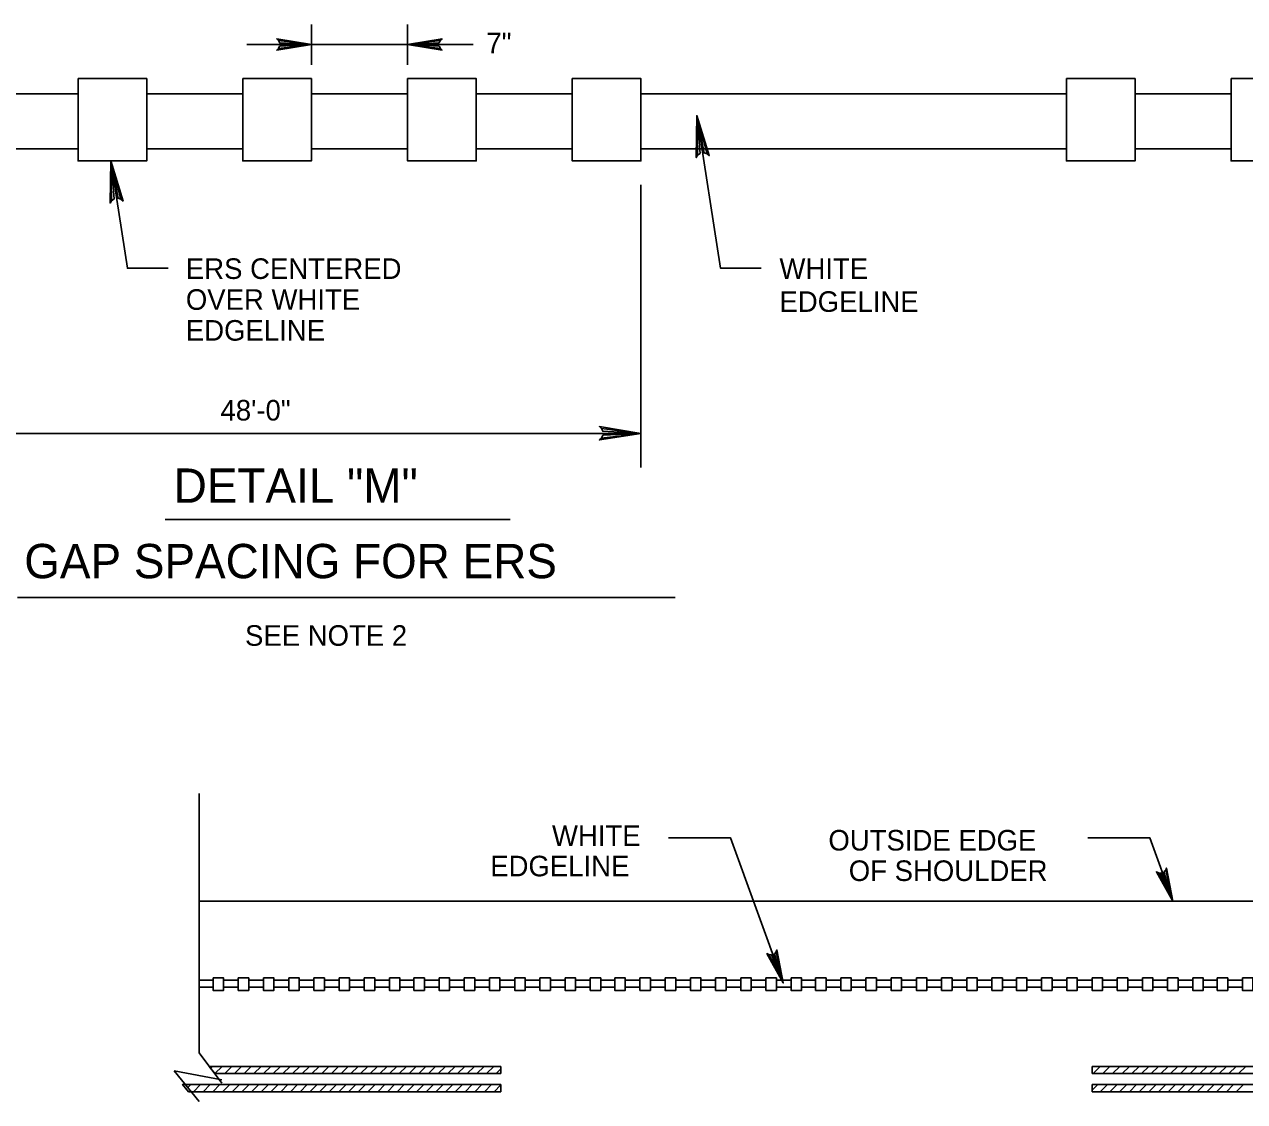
# Model space of a CAD drawing. Extents: x 632008 to 634206, y 294231 to 297795.
# Drawn here: x 632427 to 632604.8, y 296165.1 to 296322.1 of the extents above; entities that cross this region are included whole.
import ezdxf

# ---------------------------------------------------------------- set-up
doc = ezdxf.new("R2010")
doc.units = 0
for name, color, linetype in [('1', 7, 'Continuous'), ('Level 1', 7, 'Continuous'), ('Level 2', 7, 'Continuous')]:
    doc.layers.add(name, color=color, linetype=linetype)

msp = doc.modelspace()

# ---------------------------------------------------------------- linework, layer by layer
at = {"layer": '1'}
for p, q in [((632597.47, 296311.98), (632602.86, 296311.98)), ((632597.53, 296303.98), (632602.86, 296303.98)), ((632447.49, 296249.95), (632497.75, 296249.95)), ((632425.96, 296238.55), (632521.83, 296238.55)), ((632454.11, 296169.94), (632454.38, 296170.21)), ((632454.73, 296169.15), (632455.79, 296170.21)), ((632456.15, 296169.15), (632457.2, 296170.21)), ((632457.56, 296169.15), (632458.62, 296170.21)), ((632458.97, 296169.15), (632460.03, 296170.21)), ((632460.39, 296169.15), (632461.45, 296170.21)), ((632461.8, 296169.15), (632462.86, 296170.21)), ((632463.22, 296169.15), (632464.28, 296170.21)), ((632464.63, 296169.15), (632465.69, 296170.21)), ((632466.05, 296169.15), (632467.1, 296170.21)), ((632467.46, 296169.15), (632468.52, 296170.21)), ((632468.87, 296169.15), (632469.93, 296170.21)), ((632470.29, 296169.15), (632471.35, 296170.21)), ((632471.7, 296169.15), (632472.76, 296170.21)), ((632473.12, 296169.15), (632474.17, 296170.21)), ((632474.53, 296169.15), (632475.59, 296170.21)), ((632475.95, 296169.15), (632477, 296170.21)), ((632477.36, 296169.15), (632478.42, 296170.21)), ((632478.77, 296169.15), (632479.83, 296170.21)), ((632480.19, 296169.15), (632481.25, 296170.21)), ((632481.6, 296169.15), (632482.66, 296170.21)), ((632483.02, 296169.15), (632484.07, 296170.21)), ((632484.43, 296169.15), (632485.49, 296170.21)), ((632485.84, 296169.15), (632486.9, 296170.21)), ((632487.26, 296169.15), (632488.32, 296170.21)), ((632488.67, 296169.15), (632489.73, 296170.21)), ((632490.09, 296169.15), (632491.15, 296170.21)), ((632491.5, 296169.15), (632492.56, 296170.21)), ((632492.92, 296169.15), (632493.97, 296170.21)), ((632494.33, 296169.15), (632495.39, 296170.21)), ((632496.42, 296169.15), (632496.42, 296170.21)), ((632582.58, 296169.15), (632582.58, 296170.21)), ((632582.73, 296169.15), (632583.79, 296170.21)), ((632584.14, 296169.15), (632585.2, 296170.21)), ((632585.56, 296169.15), (632586.62, 296170.21)), ((632586.97, 296169.15), (632588.03, 296170.21)), ((632588.39, 296169.15), (632589.45, 296170.21)), ((632589.8, 296169.15), (632590.86, 296170.21)), ((632591.22, 296169.15), (632592.28, 296170.21)), ((632592.63, 296169.15), (632593.69, 296170.21)), ((632594.04, 296169.15), (632595.1, 296170.21)), ((632595.46, 296169.15), (632596.52, 296170.21)), ((632596.87, 296169.15), (632597.93, 296170.21)), ((632598.29, 296169.15), (632599.35, 296170.21)), ((632599.7, 296169.15), (632600.76, 296170.21)), ((632601.12, 296169.15), (632602.18, 296170.21)), ((632602.53, 296169.15), (632603.59, 296170.21)), ((632603.94, 296169.15), (632605, 296170.21)), ((632495.74, 296169.15), (632496.42, 296169.83)), ((632450.76, 296167.11), (632451.22, 296167.57)), ((632451.58, 296166.51), (632452.64, 296167.57)), ((632452.99, 296166.51), (632454.05, 296167.57)), ((632454.41, 296166.51), (632455.46, 296167.57)), ((632455.82, 296166.51), (632456.88, 296167.57)), ((632457.24, 296166.51), (632458.29, 296167.57)), ((632458.65, 296166.51), (632459.71, 296167.57)), ((632460.06, 296166.51), (632461.12, 296167.57)), ((632461.48, 296166.51), (632462.54, 296167.57)), ((632462.89, 296166.51), (632463.95, 296167.57)), ((632464.31, 296166.51), (632465.36, 296167.57)), ((632465.72, 296166.51), (632466.78, 296167.57)), ((632467.13, 296166.51), (632468.19, 296167.57)), ((632468.55, 296166.51), (632469.61, 296167.57)), ((632469.96, 296166.51), (632471.02, 296167.57)), ((632471.38, 296166.51), (632472.43, 296167.57)), ((632472.79, 296166.51), (632473.85, 296167.57)), ((632474.21, 296166.51), (632475.26, 296167.57)), ((632475.62, 296166.51), (632476.68, 296167.57)), ((632477.03, 296166.51), (632478.09, 296167.57)), ((632478.45, 296166.51), (632479.51, 296167.57)), ((632479.86, 296166.51), (632480.92, 296167.57)), ((632481.28, 296166.51), (632482.33, 296167.57)), ((632482.69, 296166.51), (632483.75, 296167.57)), ((632484.11, 296166.51), (632485.16, 296167.57)), ((632485.52, 296166.51), (632486.58, 296167.57)), ((632486.93, 296166.51), (632487.99, 296167.57)), ((632488.35, 296166.51), (632489.41, 296167.57)), ((632489.76, 296166.51), (632490.82, 296167.57)), ((632491.18, 296166.51), (632492.23, 296167.57)), ((632492.59, 296166.51), (632493.65, 296167.57)), ((632494, 296166.51), (632495.06, 296167.57)), ((632495.42, 296166.51), (632496.42, 296167.52)), ((632496.42, 296166.51), (632496.42, 296167.57)), ((632582.58, 296166.51), (632582.58, 296167.57)), ((632582.58, 296166.73), (632583.42, 296167.57)), ((632583.78, 296166.51), (632584.84, 296167.57)), ((632585.2, 296166.51), (632586.25, 296167.57)), ((632586.61, 296166.51), (632587.67, 296167.57)), ((632588.03, 296166.51), (632589.08, 296167.57)), ((632589.44, 296166.51), (632590.5, 296167.57)), ((632590.85, 296166.51), (632591.91, 296167.57)), ((632592.27, 296166.51), (632593.32, 296167.57)), ((632593.68, 296166.51), (632594.74, 296167.57)), ((632595.1, 296166.51), (632596.15, 296167.57)), ((632596.51, 296166.51), (632597.57, 296167.57)), ((632597.93, 296166.51), (632598.98, 296167.57)), ((632599.34, 296166.51), (632600.4, 296167.57)), ((632600.75, 296166.51), (632601.81, 296167.57)), ((632602.17, 296166.51), (632603.22, 296167.57)), ((632603.58, 296166.51), (632604.64, 296167.57))]:
    msp.add_line(p, q, dxfattribs=at)
for points in [[(632496.42, 296169.15), (632454.7, 296169.15), (632453.9, 296170.21), (632496.42, 296170.21)], [(632582.58, 296170.21), (632627.93, 296170.21), (632628.72, 296169.15), (632582.58, 296169.15)], [(632496.42, 296166.51), (632450.88, 296166.51), (632450.02, 296167.57), (632496.42, 296167.57)], [(632582.58, 296167.57), (632624.29, 296167.57), (632625.14, 296166.51), (632582.58, 296166.51)]]:
    msp.add_lwpolyline(points, dxfattribs=at)
at = {"layer": 'Level 1'}
for p, q in [((632434.78, 296311.98), (632420.77, 296311.98)), ((632458.79, 296311.98), (632444.78, 296311.98)), ((632482.8, 296311.98), (632468.79, 296311.98)), ((632506.81, 296311.98), (632492.81, 296311.98)), ((632578.85, 296311.98), (632516.82, 296311.98)), ((632597.47, 296311.98), (632588.85, 296311.98)), ((632434.78, 296303.98), (632420.77, 296303.98)), ((632458.79, 296303.98), (632444.78, 296303.98)), ((632482.8, 296303.98), (632468.79, 296303.98)), ((632506.81, 296303.98), (632492.81, 296303.98)), ((632578.85, 296303.98), (632516.82, 296303.98)), ((632597.53, 296303.98), (632588.85, 296303.98))]:
    msp.add_line(p, q, dxfattribs=at)
at = {"layer": 'Level 2'}
for p, q in [((632468.79, 296322.11), (632468.79, 296316.2)), ((632482.8, 296322.11), (632482.8, 296316.2)), ((632459.4, 296319.18), (632492.37, 296319.18)), ((632516.82, 296298.73), (632516.82, 296257.49)), ((632410.77, 296262.49), (632516.82, 296262.49)), ((632452.42, 296172.19), (632452.42, 296210)), ((632626.45, 296194.3), (632452.42, 296194.3)), ((632454.46, 296182.78), (632452.42, 296182.78)), ((632458.13, 296182.78), (632455.99, 296182.78)), ((632461.8, 296182.78), (632459.66, 296182.78)), ((632465.48, 296182.78), (632463.33, 296182.78)), ((632469.15, 296182.78), (632467.01, 296182.78)), ((632472.82, 296182.78), (632470.68, 296182.78)), ((632476.5, 296182.78), (632474.35, 296182.78)), ((632480.17, 296182.78), (632478.03, 296182.78)), ((632483.73, 296182.78), (632481.7, 296182.78)), ((632487.41, 296182.78), (632485.26, 296182.78)), ((632491.08, 296182.78), (632488.94, 296182.78)), ((632494.75, 296182.78), (632492.61, 296182.78)), ((632498.42, 296182.78), (632496.28, 296182.78)), ((632502.1, 296182.78), (632499.96, 296182.78)), ((632505.77, 296182.78), (632503.63, 296182.78)), ((632509.44, 296182.78), (632507.3, 296182.78)), ((632513.01, 296182.78), (632510.97, 296182.78)), ((632516.68, 296182.78), (632514.54, 296182.78)), ((632520.35, 296182.78), (632518.21, 296182.78)), ((632524.03, 296182.78), (632521.89, 296182.78)), ((632527.7, 296182.78), (632525.56, 296182.78)), ((632531.37, 296182.78), (632529.23, 296182.78)), ((632535.05, 296182.78), (632532.9, 296182.78)), ((632538.72, 296182.78), (632536.58, 296182.78)), ((632542.28, 296182.78), (632540.25, 296182.78)), ((632545.96, 296182.78), (632543.82, 296182.78)), ((632549.63, 296182.78), (632547.49, 296182.78)), ((632553.3, 296182.78), (632551.16, 296182.78)), ((632556.98, 296182.78), (632554.83, 296182.78)), ((632560.65, 296182.78), (632558.51, 296182.78)), ((632564.32, 296182.78), (632562.18, 296182.78)), ((632567.99, 296182.78), (632565.85, 296182.78)), ((632571.56, 296182.78), (632569.52, 296182.78)), ((632575.23, 296182.78), (632573.09, 296182.78)), ((632578.91, 296182.78), (632576.76, 296182.78)), ((632582.58, 296182.78), (632580.44, 296182.78)), ((632586.25, 296182.78), (632584.11, 296182.78)), ((632589.92, 296182.78), (632587.78, 296182.78)), ((632593.6, 296182.78), (632591.45, 296182.78)), ((632597.27, 296182.78), (632595.13, 296182.78)), ((632600.84, 296182.78), (632598.8, 296182.78)), ((632604.51, 296182.78), (632602.37, 296182.78)), ((632454.46, 296181.76), (632452.42, 296181.76)), ((632458.13, 296181.76), (632455.99, 296181.76)), ((632461.8, 296181.76), (632459.66, 296181.76)), ((632465.48, 296181.76), (632463.33, 296181.76)), ((632469.15, 296181.76), (632467.01, 296181.76)), ((632472.82, 296181.76), (632470.68, 296181.76)), ((632476.5, 296181.76), (632474.35, 296181.76)), ((632480.17, 296181.76), (632478.03, 296181.76)), ((632483.73, 296181.76), (632481.7, 296181.76)), ((632487.41, 296181.76), (632485.26, 296181.76)), ((632491.08, 296181.76), (632488.94, 296181.76)), ((632494.75, 296181.76), (632492.61, 296181.76)), ((632498.42, 296181.76), (632496.28, 296181.76)), ((632502.1, 296181.76), (632499.96, 296181.76)), ((632505.77, 296181.76), (632503.63, 296181.76)), ((632509.44, 296181.76), (632507.3, 296181.76)), ((632513.01, 296181.76), (632510.97, 296181.76)), ((632516.68, 296181.76), (632514.54, 296181.76)), ((632520.35, 296181.76), (632518.21, 296181.76)), ((632524.03, 296181.76), (632521.89, 296181.76)), ((632527.7, 296181.76), (632525.56, 296181.76)), ((632531.37, 296181.76), (632529.23, 296181.76)), ((632535.05, 296181.76), (632532.9, 296181.76)), ((632538.72, 296181.76), (632536.58, 296181.76)), ((632542.28, 296181.76), (632540.25, 296181.76)), ((632545.96, 296181.76), (632543.82, 296181.76)), ((632549.63, 296181.76), (632547.49, 296181.76)), ((632553.3, 296181.76), (632551.16, 296181.76)), ((632556.98, 296181.76), (632554.83, 296181.76)), ((632560.65, 296181.76), (632558.51, 296181.76)), ((632564.32, 296181.76), (632562.18, 296181.76)), ((632567.99, 296181.76), (632565.85, 296181.76)), ((632571.56, 296181.76), (632569.52, 296181.76)), ((632575.23, 296181.76), (632573.09, 296181.76)), ((632578.91, 296181.76), (632576.76, 296181.76)), ((632582.58, 296181.76), (632580.44, 296181.76)), ((632586.25, 296181.76), (632584.11, 296181.76)), ((632589.92, 296181.76), (632587.78, 296181.76)), ((632593.6, 296181.76), (632591.45, 296181.76)), ((632597.27, 296181.76), (632595.13, 296181.76)), ((632600.84, 296181.76), (632598.8, 296181.76)), ((632604.51, 296181.76), (632602.37, 296181.76)), ((632455.74, 296167.76), (632452.42, 296172.19)), ((632448.77, 296169.57), (632455.74, 296168.22)), ((632452.42, 296165.07), (632448.77, 296169.57))]:
    msp.add_line(p, q, dxfattribs=at)
for points in [[(632463.98, 296318.58), (632464.16, 296318.93), (632468.78, 296319.18), (632463.98, 296318.58), (632463.74, 296318.37), (632468.78, 296319.18), (632464.17, 296319.41), (632464, 296319.75), (632468.78, 296319.18), (632463.74, 296319.98), (632464, 296319.75)], [(632487.59, 296318.58), (632487.41, 296318.93), (632482.79, 296319.18), (632487.59, 296318.58), (632487.83, 296318.37), (632482.79, 296319.18), (632487.41, 296319.41), (632487.57, 296319.75), (632482.79, 296319.18), (632487.83, 296319.98), (632487.57, 296319.75)], [(632525.08, 296303.03), (632525.46, 296303.3), (632524.97, 296308.82), (632525.08, 296303.03), (632524.88, 296302.7), (632524.97, 296308.82), (632526.04, 296303.38), (632526.47, 296303.24), (632524.97, 296308.82), (632526.79, 296302.98), (632526.47, 296303.24)], [(632534.36, 296286.57), (632528.44, 296286.57), (632524.97, 296308.82)], [(632439.64, 296296.4), (632440.02, 296296.67), (632439.53, 296302.2), (632439.64, 296296.4), (632439.44, 296296.07), (632439.53, 296302.2), (632440.6, 296296.76), (632441.03, 296296.62), (632439.53, 296302.2), (632441.35, 296296.35), (632441.03, 296296.62)], [(632447.89, 296286.57), (632441.96, 296286.57), (632439.53, 296302.2)], [(632511.07, 296263.22), (632511.27, 296262.8), (632516.82, 296262.49), (632511.07, 296263.22), (632510.77, 296263.47), (632516.82, 296262.49), (632511.28, 296262.22), (632511.08, 296261.81), (632516.82, 296262.49), (632510.77, 296261.53), (632511.08, 296261.81)], [(632520.85, 296203.5), (632529.89, 296203.5), (632537.57, 296182.38)], [(632581.97, 296203.5), (632591.01, 296203.5), (632594.36, 296194.3)], [(632593.32, 296198.82), (632593.07, 296198.55), (632594.36, 296194.3), (632593.32, 296198.82), (632593.43, 296199.11), (632594.36, 296194.3), (632592.63, 296198.39), (632592.27, 296198.43), (632594.36, 296194.3), (632591.97, 296198.58), (632592.27, 296198.43)], [(632536.54, 296186.9), (632536.29, 296186.63), (632537.57, 296182.38), (632536.54, 296186.9), (632536.65, 296187.19), (632537.57, 296182.38), (632535.85, 296186.47), (632535.49, 296186.5), (632537.57, 296182.38), (632535.19, 296186.66), (632535.49, 296186.5)]]:
    msp.add_lwpolyline(points, dxfattribs=at)
for points in [[(632434.78, 296314.2), (632444.78, 296314.2), (632444.78, 296302.2), (632434.78, 296302.2)], [(632434.78, 296314.2), (632444.78, 296314.2), (632444.78, 296302.2), (632434.78, 296302.2)], [(632458.79, 296314.2), (632468.79, 296314.2), (632468.79, 296302.2), (632458.79, 296302.2)], [(632482.8, 296314.2), (632492.81, 296314.2), (632492.81, 296302.2), (632482.8, 296302.2)], [(632506.81, 296314.2), (632516.82, 296314.2), (632516.82, 296302.2), (632506.81, 296302.2)], [(632578.85, 296314.2), (632588.85, 296314.2), (632588.85, 296302.2), (632578.85, 296302.2)], [(632602.86, 296314.2), (632612.86, 296314.2), (632612.86, 296302.2), (632602.86, 296302.2)], [(632454.46, 296183.11), (632455.99, 296183.11), (632455.99, 296181.27), (632454.46, 296181.27)], [(632458.13, 296183.11), (632459.66, 296183.11), (632459.66, 296181.27), (632458.13, 296181.27)], [(632461.8, 296183.11), (632463.33, 296183.11), (632463.33, 296181.27), (632461.8, 296181.27)], [(632465.48, 296183.11), (632467.01, 296183.11), (632467.01, 296181.27), (632465.48, 296181.27)], [(632465.48, 296183.11), (632467.01, 296183.11), (632467.01, 296181.27), (632465.48, 296181.27)], [(632469.15, 296183.11), (632470.68, 296183.11), (632470.68, 296181.27), (632469.15, 296181.27)], [(632469.15, 296183.11), (632470.68, 296183.11), (632470.68, 296181.27), (632469.15, 296181.27)], [(632472.82, 296183.11), (632474.35, 296183.11), (632474.35, 296181.27), (632472.82, 296181.27)], [(632472.82, 296183.11), (632474.35, 296183.11), (632474.35, 296181.27), (632472.82, 296181.27)], [(632476.5, 296183.11), (632478.03, 296183.11), (632478.03, 296181.27), (632476.5, 296181.27)], [(632476.5, 296183.11), (632478.03, 296183.11), (632478.03, 296181.27), (632476.5, 296181.27)], [(632480.17, 296183.11), (632481.7, 296183.11), (632481.7, 296181.27), (632480.17, 296181.27)], [(632480.17, 296183.11), (632481.7, 296183.11), (632481.7, 296181.27), (632480.17, 296181.27)], [(632483.73, 296183.11), (632485.26, 296183.11), (632485.26, 296181.27), (632483.73, 296181.27)], [(632487.41, 296183.11), (632488.94, 296183.11), (632488.94, 296181.27), (632487.41, 296181.27)], [(632491.08, 296183.11), (632492.61, 296183.11), (632492.61, 296181.27), (632491.08, 296181.27)], [(632494.75, 296183.11), (632496.28, 296183.11), (632496.28, 296181.27), (632494.75, 296181.27)], [(632494.75, 296183.11), (632496.28, 296183.11), (632496.28, 296181.27), (632494.75, 296181.27)], [(632498.42, 296183.11), (632499.96, 296183.11), (632499.96, 296181.27), (632498.42, 296181.27)], [(632498.42, 296183.11), (632499.96, 296183.11), (632499.96, 296181.27), (632498.42, 296181.27)], [(632502.1, 296183.11), (632503.63, 296183.11), (632503.63, 296181.27), (632502.1, 296181.27)], [(632502.1, 296183.11), (632503.63, 296183.11), (632503.63, 296181.27), (632502.1, 296181.27)], [(632505.77, 296183.11), (632507.3, 296183.11), (632507.3, 296181.27), (632505.77, 296181.27)], [(632505.77, 296183.11), (632507.3, 296183.11), (632507.3, 296181.27), (632505.77, 296181.27)], [(632509.44, 296183.11), (632510.97, 296183.11), (632510.97, 296181.27), (632509.44, 296181.27)], [(632509.44, 296183.11), (632510.97, 296183.11), (632510.97, 296181.27), (632509.44, 296181.27)], [(632513.01, 296183.11), (632514.54, 296183.11), (632514.54, 296181.27), (632513.01, 296181.27)], [(632516.68, 296183.11), (632518.21, 296183.11), (632518.21, 296181.27), (632516.68, 296181.27)], [(632520.35, 296183.11), (632521.89, 296183.11), (632521.89, 296181.27), (632520.35, 296181.27)], [(632524.03, 296183.11), (632525.56, 296183.11), (632525.56, 296181.27), (632524.03, 296181.27)], [(632524.03, 296183.11), (632525.56, 296183.11), (632525.56, 296181.27), (632524.03, 296181.27)], [(632527.7, 296183.11), (632529.23, 296183.11), (632529.23, 296181.27), (632527.7, 296181.27)], [(632527.7, 296183.11), (632529.23, 296183.11), (632529.23, 296181.27), (632527.7, 296181.27)], [(632531.37, 296183.11), (632532.9, 296183.11), (632532.9, 296181.27), (632531.37, 296181.27)], [(632531.37, 296183.11), (632532.9, 296183.11), (632532.9, 296181.27), (632531.37, 296181.27)], [(632535.05, 296183.11), (632536.58, 296183.11), (632536.58, 296181.27), (632535.05, 296181.27)], [(632535.05, 296183.11), (632536.58, 296183.11), (632536.58, 296181.27), (632535.05, 296181.27)], [(632538.72, 296183.11), (632540.25, 296183.11), (632540.25, 296181.27), (632538.72, 296181.27)], [(632538.72, 296183.11), (632540.25, 296183.11), (632540.25, 296181.27), (632538.72, 296181.27)], [(632542.28, 296183.11), (632543.82, 296183.11), (632543.82, 296181.27), (632542.28, 296181.27)], [(632545.96, 296183.11), (632547.49, 296183.11), (632547.49, 296181.27), (632545.96, 296181.27)], [(632549.63, 296183.11), (632551.16, 296183.11), (632551.16, 296181.27), (632549.63, 296181.27)], [(632553.3, 296183.11), (632554.83, 296183.11), (632554.83, 296181.27), (632553.3, 296181.27)], [(632553.3, 296183.11), (632554.83, 296183.11), (632554.83, 296181.27), (632553.3, 296181.27)], [(632556.98, 296183.11), (632558.51, 296183.11), (632558.51, 296181.27), (632556.98, 296181.27)], [(632556.98, 296183.11), (632558.51, 296183.11), (632558.51, 296181.27), (632556.98, 296181.27)], [(632560.65, 296183.11), (632562.18, 296183.11), (632562.18, 296181.27), (632560.65, 296181.27)], [(632560.65, 296183.11), (632562.18, 296183.11), (632562.18, 296181.27), (632560.65, 296181.27)], [(632564.32, 296183.11), (632565.85, 296183.11), (632565.85, 296181.27), (632564.32, 296181.27)], [(632564.32, 296183.11), (632565.85, 296183.11), (632565.85, 296181.27), (632564.32, 296181.27)], [(632567.99, 296183.11), (632569.52, 296183.11), (632569.52, 296181.27), (632567.99, 296181.27)], [(632567.99, 296183.11), (632569.52, 296183.11), (632569.52, 296181.27), (632567.99, 296181.27)], [(632571.56, 296183.11), (632573.09, 296183.11), (632573.09, 296181.27), (632571.56, 296181.27)], [(632575.23, 296183.11), (632576.76, 296183.11), (632576.76, 296181.27), (632575.23, 296181.27)], [(632578.91, 296183.11), (632580.44, 296183.11), (632580.44, 296181.27), (632578.91, 296181.27)], [(632582.58, 296183.11), (632584.11, 296183.11), (632584.11, 296181.27), (632582.58, 296181.27)], [(632582.58, 296183.11), (632584.11, 296183.11), (632584.11, 296181.27), (632582.58, 296181.27)], [(632586.25, 296183.11), (632587.78, 296183.11), (632587.78, 296181.27), (632586.25, 296181.27)], [(632586.25, 296183.11), (632587.78, 296183.11), (632587.78, 296181.27), (632586.25, 296181.27)], [(632589.92, 296183.11), (632591.45, 296183.11), (632591.45, 296181.27), (632589.92, 296181.27)], [(632589.92, 296183.11), (632591.45, 296183.11), (632591.45, 296181.27), (632589.92, 296181.27)], [(632593.6, 296183.11), (632595.13, 296183.11), (632595.13, 296181.27), (632593.6, 296181.27)], [(632593.6, 296183.11), (632595.13, 296183.11), (632595.13, 296181.27), (632593.6, 296181.27)], [(632597.27, 296183.11), (632598.8, 296183.11), (632598.8, 296181.27), (632597.27, 296181.27)], [(632597.27, 296183.11), (632598.8, 296183.11), (632598.8, 296181.27), (632597.27, 296181.27)], [(632600.84, 296183.11), (632602.37, 296183.11), (632602.37, 296181.27), (632600.84, 296181.27)], [(632604.51, 296183.11), (632606.04, 296183.11), (632606.04, 296181.27), (632604.51, 296181.27)]]:
    msp.add_lwpolyline(points, close=True, dxfattribs=at)

# ---------------------------------------------------------------- texts
for s, height, p in [('7"', 3, (632494.3, 296317.88)), ('ERS CENTERED', 3, (632450.49, 296285)), ('WHITE', 3, (632537.02, 296285)), ('OVER WHITE', 3, (632450.49, 296280.5)), ('EDGELINE', 3, (632537.02, 296280.2)), ('EDGELINE', 3, (632450.49, 296276)), ('48\'-0"', 3, (632455.54, 296264.36)), ('DETAIL "M"', 5, (632448.72, 296252.37)), ('GAP SPACING FOR ERS', 5, (632426.93, 296241.37)), ('SEE NOTE 2', 3, (632459.11, 296231.52)), ('WHITE', 3, (632503.86, 296202.35)), ('OUTSIDE EDGE', 3, (632544.15, 296201.67)), ('EDGELINE', 3, (632494.86, 296197.91)), ('OF SHOULDER', 3, (632547.12, 296197.23))]:
    msp.add_text(s, height=height, dxfattribs=at).set_placement(p)

doc.saveas('drawing.dxf')
